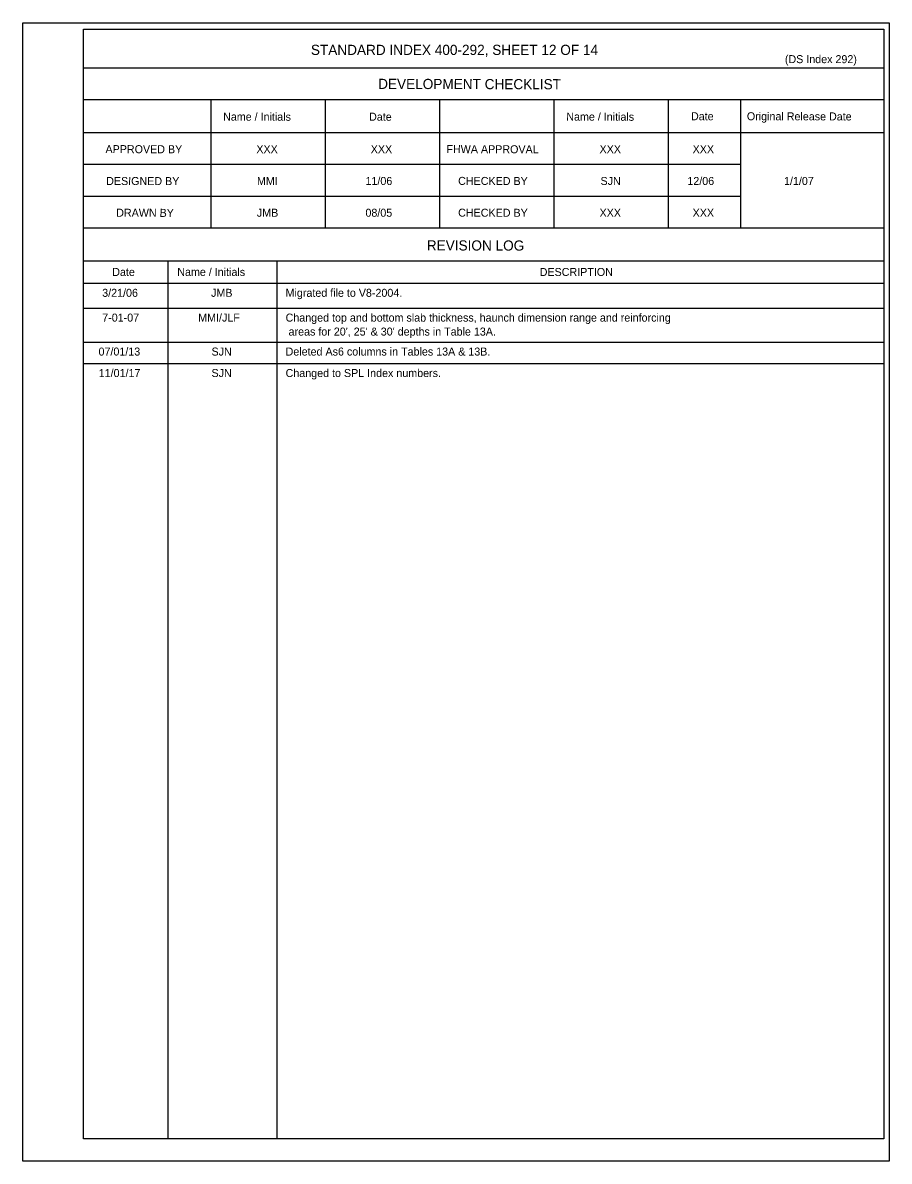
# Model space of a CAD drawing. Extents: x 10346.98 to 10349.19, y 76371.36 to 76372.62.
# Drawn here: x 10348.508 to 10349.19, y 76371.667 to 76372.563 of the extents above; entities that cross this region are included whole.
import ezdxf

# ---------------------------------------------------------------- set-up
doc = ezdxf.new("R2010")
doc.units = 0
for name, color, linetype in [('AdhocPoint_dp', 7, 'Continuous'), ('Border', 7, 'Continuous'), ('PlotBorder_dp', 7, 'Continuous')]:
    doc.layers.add(name, color=color, linetype=linetype)

msp = doc.modelspace()

# ---------------------------------------------------------------- linework, layer by layer
at = {"layer": 'Border'}
for p, q in [((10349.18582, 76372.52706), (10348.55623, 76372.52706)), ((10349.18582, 76372.50206), (10348.55623, 76372.50206)), ((10348.65623, 76372.50206), (10348.65623, 76372.40119)), ((10348.74623, 76372.50206), (10348.74623, 76372.40119)), ((10348.83623, 76372.50206), (10348.83623, 76372.40119)), ((10348.92623, 76372.50206), (10348.92623, 76372.40119)), ((10349.01623, 76372.50206), (10349.01623, 76372.40119)), ((10349.07295, 76372.50206), (10349.07295, 76372.40119)), ((10349.18582, 76372.47619), (10348.55623, 76372.47619)), ((10349.07295, 76372.45119), (10348.55623, 76372.45119)), ((10349.07295, 76372.42619), (10348.55623, 76372.42619)), ((10349.18582, 76372.40119), (10348.55623, 76372.40119)), ((10349.18582, 76372.37532), (10348.55623, 76372.37532)), ((10348.62249, 76372.37532), (10348.62249, 76371.68449)), ((10348.70819, 76372.37532), (10348.70819, 76371.68449)), ((10349.18582, 76372.3577), (10348.55623, 76372.3577)), ((10348.5084, 76371.66695), (10348.5084, 76371.66695))]:
    msp.add_line(p, q, dxfattribs=at)
for points in [[(10348.5084, 76372.56278), (10349.19007, 76372.56278), (10349.19007, 76371.66695), (10348.5084, 76371.66695)], [(10348.55624, 76372.5577), (10349.18582, 76372.5577), (10349.18582, 76371.68449), (10348.55624, 76371.68449)]]:
    msp.add_lwpolyline(points, close=True, dxfattribs=at)
at = {"layer": 'PlotBorder_dp'}
for p, q in [((10348.55624, 76372.3382), (10349.18582, 76372.3382)), ((10348.55624, 76372.31147), (10349.18582, 76372.31147)), ((10348.55624, 76372.29458), (10349.18582, 76372.29458))]:
    msp.add_line(p, q, dxfattribs=at)

# ---------------------------------------------------------------- texts
at = {"layer": 'AdhocPoint_dp'}
for s, height, p in [('STANDARD INDEX 400-292, SHEET 12 OF 14', 0.008, (10348.73507, 76372.53745)), ('(DS Index 292)', 0.0063, (10349.10798, 76372.53101)), ('XXX', 0.0063, (10348.69217, 76372.46015)), ('XXX', 0.0063, (10348.78217, 76372.46015)), ('XXX', 0.0063, (10348.96217, 76372.46015)), ('XXX', 0.0063, (10349.0354, 76372.46015)), ('MMI', 0.0063, (10348.69266, 76372.43515)), ('11/06', 0.0063, (10348.77803, 76372.43515)), ('SJN', 0.0063, (10348.96293, 76372.43515)), ('12/06', 0.0063, (10349.03126, 76372.43515)), ('1/1/07', 0.0063, (10349.10732, 76372.43515)), ('JMB', 0.0063, (10348.69258, 76372.41015)), ('08/05', 0.0063, (10348.77799, 76372.41015)), ('XXX', 0.0063, (10348.96217, 76372.41015)), ('XXX', 0.0063, (10349.0354, 76372.41015)), ('DESCRIPTION', 0.0063, (10348.91509, 76372.36354)), ('3/21/06', 0.0063, (10348.5709, 76372.34714)), ('JMB', 0.0063, (10348.65654, 76372.34714)), ('Migrated file to V8-2004.', 0.0063, (10348.71517, 76372.34714)), ('7-01-07', 0.0063, (10348.57092, 76372.32763)), ('MMI/JLF', 0.0063, (10348.64641, 76372.32763)), ('Changed top and bottom slab thickness, haunch dimension range and reinforcing', 0.0063, (10348.71518, 76372.32763)), (" areas for 20', 25' & 30' depths in Table 13A. ", 0.0063, (10348.71518, 76372.31664)), ('07/01/13', 0.0063, (10348.56801, 76372.30091)), ('SJN', 0.0063, (10348.6569, 76372.30091)), ('Deleted As6 columns in Tables 13A & 13B.', 0.0063, (10348.71518, 76372.30091)), ('11/01/17', 0.0063, (10348.56815, 76372.28401)), ('Changed to SPL Index numbers.', 0.0063, (10348.71518, 76372.28401)), ('SJN', 0.0063, (10348.6569, 76372.28401))]:
    msp.add_text(s, height=height, dxfattribs=at).set_placement(p)
for s, height, p in [('DEVELOPMENT CHECKLIST', 0.008, (10348.78798, 76372.51071)), ('Name / Initials', 0.0063, (10348.666, 76372.48578)), ('Date', 0.0063, (10348.78083, 76372.48573)), ('Name / Initials', 0.0063, (10348.936, 76372.48578)), ('Date', 0.0063, (10349.03411, 76372.48609)), ('Original Release Date', 0.0063, (10349.07807, 76372.48608)), ('APPROVED BY', 0.0063, (10348.57347, 76372.46021)), ('FHWA APPROVAL', 0.0063, (10348.8417, 76372.46021)), ('DESIGNED BY', 0.0063, (10348.574, 76372.43515)), ('CHECKED BY', 0.0063, (10348.85092, 76372.43521)), ('DRAWN BY', 0.0063, (10348.5819, 76372.41015)), ('CHECKED BY', 0.0063, (10348.85092, 76372.41021)), ('REVISION LOG', 0.008, (10348.82626, 76372.38365)), ('Date', 0.0063, (10348.5788, 76372.36356)), ('Name / Initials', 0.0063, (10348.62995, 76372.36361))]:
    msp.add_text(s, height=height, rotation=359.87563, dxfattribs=at).set_placement(p)

doc.saveas('drawing.dxf')
